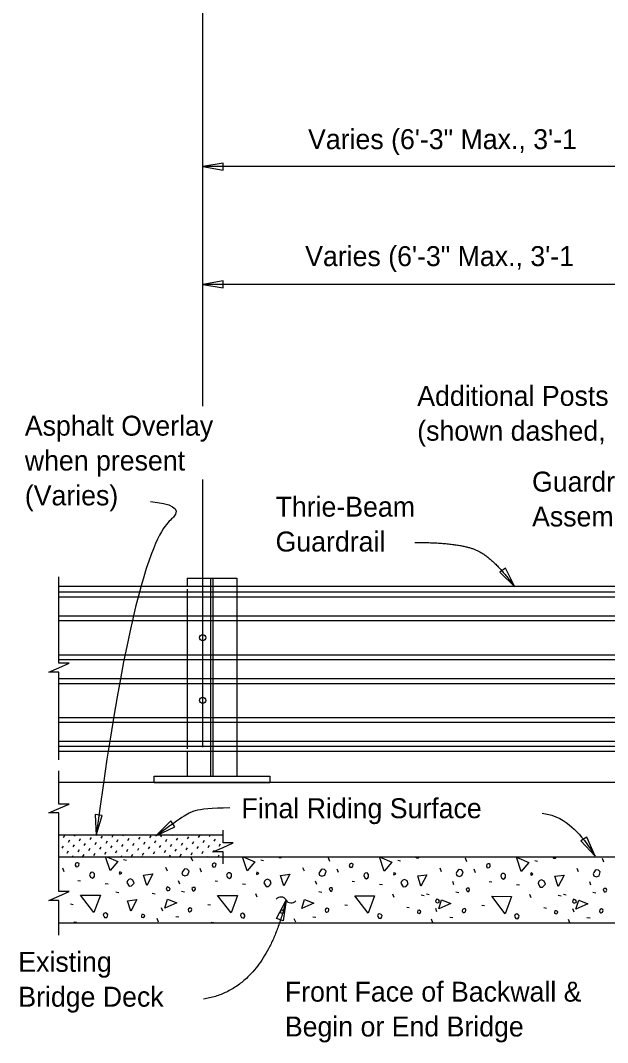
# Model space of a CAD drawing. Extents: x 21587 to 21656.3, y 56117.4 to 56157.3.
# Drawn here: x 21587.27 to 21593.21, y 56132.17 to 56142.5 of the extents above; entities that cross this region are included whole.
import ezdxf

# ---------------------------------------------------------------- set-up
doc = ezdxf.new("R2010")
doc.units = 0
for name, color, linetype in [('AdhocPoint_dp', 7, 'Continuous'), ('Border', 7, 'Continuous'), ('Patterning', 7, 'Continuous'), ('PlotBorder_dp', 7, 'Continuous'), ('SheetBorder_dp', 7, 'Continuous'), ('TextMisc', 7, 'Continuous')]:
    doc.layers.add(name, color=color, linetype=linetype)

msp = doc.modelspace()

# ---------------------------------------------------------------- linework, layer by layer
at = {"layer": 'AdhocPoint_dp'}
for p, q in [((21593.837, 56134.801), (21587.663, 56134.801)), ((21589.321, 56134.27), (21587.663, 56134.27)), ((21587.663, 56134.051), (21593.837, 56134.051)), ((21587.663, 56133.384), (21593.837, 56133.384))]:
    msp.add_line(p, q, dxfattribs=at)
at = {"layer": 'Border'}
for p, q in [((21588.96, 56136.864), (21589.46, 56136.864)), ((21588.96, 56136.864), (21588.96, 56136.78)), ((21589.46, 56136.864), (21589.46, 56136.78)), ((21599.759, 56136.78), (21587.663, 56136.78)), ((21587.663, 56136.725), (21599.759, 56136.725)), ((21587.663, 56136.676), (21599.759, 56136.676)), ((21587.663, 56136.484), (21599.759, 56136.484)), ((21587.663, 56136.435), (21599.759, 56136.435)), ((21587.663, 56136.091), (21599.759, 56136.091)), ((21587.663, 56136.043), (21599.759, 56136.043)), ((21587.663, 56135.85), (21599.759, 56135.85)), ((21587.663, 56135.802), (21599.759, 56135.802)), ((21587.663, 56135.458), (21599.759, 56135.458)), ((21587.663, 56135.41), (21599.759, 56135.41)), ((21587.663, 56135.217), (21599.759, 56135.217)), ((21587.663, 56135.169), (21599.759, 56135.169)), ((21599.759, 56135.113), (21587.663, 56135.113)), ((21588.96, 56135.114), (21588.96, 56134.864)), ((21589.46, 56135.113), (21589.46, 56134.864)), ((21588.626, 56134.864), (21589.793, 56134.864)), ((21588.626, 56134.801), (21588.626, 56134.864)), ((21588.626, 56134.801), (21589.793, 56134.801)), ((21588.96, 56134.864), (21589.46, 56134.864)), ((21589.793, 56134.864), (21589.793, 56134.801))]:
    msp.add_line(p, q, dxfattribs=at)
for centre in [(21589.116, 56136.263), (21589.116, 56135.63)]:
    msp.add_circle(centre, 0.0312, dxfattribs=at)
at = {"layer": 'Patterning'}
for p, q in [((21589.199, 56134.864), (21589.199, 56136.864)), ((21589.22, 56134.864), (21589.22, 56136.864)), ((21589.46, 56136.78), (21589.46, 56135.113)), ((21588.96, 56136.752), (21588.96, 56135.14))]:
    msp.add_line(p, q, dxfattribs=at)
at = {"layer": 'PlotBorder_dp'}
for p, q in [((21589.116, 56138.601), (21589.116, 56143.311)), ((21605.004, 56141.02), (21589.116, 56141.02)), ((21604.924, 56139.829), (21589.116, 56139.829)), ((21589.116, 56135.158), (21589.116, 56137.859))]:
    msp.add_line(p, q, dxfattribs=at)
for points in [[(21589.116, 56141.02), (21589.324, 56140.985), (21589.324, 56141.056)], [(21589.116, 56139.829), (21589.324, 56139.794), (21589.324, 56139.865)], [(21592.268, 56136.776), (21592.174, 56136.965), (21592.117, 56136.923)], [(21588.039, 56134.266), (21588.101, 56134.468), (21588.031, 56134.478)], [(21588.643, 56134.263), (21588.833, 56134.354), (21588.793, 56134.412)], [(21593.082, 56134.058), (21592.996, 56134.25), (21592.937, 56134.211)], [(21589.958, 56133.614), (21589.928, 56133.405), (21589.861, 56133.427)]]:
    msp.add_lwpolyline(points, close=True, dxfattribs=at)
for points in [[(21587.663, 56135.03), (21587.663, 56135.914), (21587.56, 56135.914), (21587.663, 56135.959), (21587.767, 56136.004), (21587.663, 56136.004), (21587.663, 56136.877)], [(21587.663, 56134.023), (21587.663, 56134.493), (21587.56, 56134.493), (21587.663, 56134.538), (21587.767, 56134.583), (21587.663, 56134.583), (21587.663, 56134.918)], [(21589.321, 56133.979), (21589.321, 56134.1), (21589.218, 56134.1), (21589.321, 56134.145), (21589.425, 56134.19), (21589.321, 56134.19), (21589.321, 56134.32)], [(21587.663, 56133.258), (21587.663, 56133.609), (21587.56, 56133.609), (21587.663, 56133.654), (21587.767, 56133.699), (21587.663, 56133.699), (21587.663, 56134.023)]]:
    msp.add_lwpolyline(points, dxfattribs=at)
for centre, start, end in [((21589.906, 56133.585), 30.0081, 141.7354), ((21590.009, 56133.644), 210.0081, 321.7354)]:
    msp.add_arc(centre, 0.0596, start, end, dxfattribs=at)
for points, degree in [([(21588.59, 56137.637), (21588.787, 56137.619), (21589.026, 56137.521), (21588.438, 56137.259), (21588.039, 56134.266)], 3), ([(21591.26, 56137.225), (21591.681, 56137.225), (21592.041, 56137.086), (21592.268, 56136.776)], 2), ([(21589.391, 56134.544), (21589.198, 56134.542), (21589.01, 56134.521), (21588.938, 56134.471), (21588.643, 56134.263)], 3), ([(21592.546, 56134.49), (21592.687, 56134.475), (21592.864, 56134.345), (21592.962, 56134.238), (21593.082, 56134.058)], 3), ([(21589.958, 56133.614), (21589.743, 56132.711), (21589.124, 56132.613)], 2)]:
    msp.add_open_spline(points, degree=degree, dxfattribs=at)
at = {"layer": 'TextMisc'}
for p, q in [((21587.71, 56134.247), (21587.723, 56134.27)), ((21587.759, 56134.199), (21587.772, 56134.221)), ((21587.821, 56134.26), (21587.826, 56134.27)), ((21587.87, 56134.212), (21587.883, 56134.234)), ((21587.918, 56134.163), (21587.931, 56134.185)), ((21587.98, 56134.225), (21587.993, 56134.247)), ((21588.029, 56134.176), (21588.042, 56134.198)), ((21588.091, 56134.237), (21588.104, 56134.26)), ((21588.14, 56134.189), (21588.153, 56134.211)), ((21588.202, 56134.25), (21588.213, 56134.27)), ((21588.25, 56134.202), (21588.263, 56134.224)), ((21588.299, 56134.153), (21588.312, 56134.175)), ((21588.312, 56134.263), (21588.316, 56134.27)), ((21588.361, 56134.215), (21588.374, 56134.237)), ((21588.41, 56134.166), (21588.423, 56134.188)), ((21588.472, 56134.228), (21588.485, 56134.25)), ((21588.52, 56134.179), (21588.533, 56134.201)), ((21588.582, 56134.241), (21588.595, 56134.263)), ((21588.631, 56134.192), (21588.644, 56134.214)), ((21588.693, 56134.253), (21588.702, 56134.27)), ((21588.742, 56134.205), (21588.755, 56134.227)), ((21588.791, 56134.156), (21588.804, 56134.178)), ((21588.804, 56134.266), (21588.806, 56134.27)), ((21588.852, 56134.218), (21588.865, 56134.24)), ((21588.901, 56134.169), (21588.914, 56134.191)), ((21588.963, 56134.231), (21588.976, 56134.253)), ((21589.012, 56134.182), (21589.025, 56134.204)), ((21589.074, 56134.244), (21589.087, 56134.266)), ((21589.122, 56134.195), (21589.135, 56134.217)), ((21589.184, 56134.256), (21589.192, 56134.27)), ((21589.233, 56134.208), (21589.246, 56134.23)), ((21589.282, 56134.159), (21589.295, 56134.181)), ((21589.295, 56134.269), (21589.295, 56134.27)), ((21587.697, 56134.137), (21587.71, 56134.159)), ((21587.746, 56134.088), (21587.759, 56134.11)), ((21587.808, 56134.15), (21587.821, 56134.172)), ((21587.857, 56134.101), (21587.87, 56134.123)), ((21587.906, 56134.052), (21587.918, 56134.074)), ((21587.967, 56134.114), (21587.98, 56134.136)), ((21588.016, 56134.065), (21588.029, 56134.087)), ((21588.078, 56134.127), (21588.091, 56134.149)), ((21588.127, 56134.078), (21588.14, 56134.1)), ((21588.189, 56134.14), (21588.202, 56134.162)), ((21588.237, 56134.091), (21588.25, 56134.113)), ((21588.348, 56134.104), (21588.361, 56134.126)), ((21588.397, 56134.055), (21588.41, 56134.078)), ((21588.459, 56134.117), (21588.472, 56134.139)), ((21588.508, 56134.068), (21588.52, 56134.09)), ((21588.569, 56134.13), (21588.582, 56134.152)), ((21588.618, 56134.081), (21588.631, 56134.103)), ((21588.68, 56134.143), (21588.693, 56134.165)), ((21588.729, 56134.094), (21588.742, 56134.116)), ((21588.839, 56134.107), (21588.852, 56134.129)), ((21588.888, 56134.058), (21588.901, 56134.081)), ((21588.95, 56134.12), (21588.963, 56134.142)), ((21588.999, 56134.071), (21589.012, 56134.093)), ((21589.061, 56134.133), (21589.074, 56134.155)), ((21589.109, 56134.084), (21589.122, 56134.106)), ((21589.171, 56134.146), (21589.184, 56134.168)), ((21589.22, 56134.097), (21589.233, 56134.119)), ((21589.271, 56134.051), (21589.282, 56134.071)), ((21589.331, 56134.11), (21589.331, 56134.11)), ((21587.802, 56134.051), (21587.808, 56134.062)), ((21588.188, 56134.051), (21588.189, 56134.052)), ((21588.291, 56134.051), (21588.299, 56134.065)), ((21588.317, 56134.024), (21588.345, 56134.017)), ((21588.678, 56134.051), (21588.68, 56134.055)), ((21588.781, 56134.051), (21588.791, 56134.068)), ((21589.015, 56134.008), (21589.001, 56134.043)), ((21589.167, 56134.051), (21589.171, 56134.058)), ((21589.702, 56134.02), (21589.73, 56134.013)), ((21590.4, 56134.004), (21590.386, 56134.04)), ((21591.086, 56134.017), (21591.114, 56134.01)), ((21591.784, 56134.001), (21591.77, 56134.036)), ((21592.471, 56134.013), (21592.499, 56134.006)), ((21593.169, 56133.997), (21593.155, 56134.033)), ((21587.718, 56133.899), (21587.704, 56133.934)), ((21588.759, 56133.907), (21588.745, 56133.942)), ((21589.103, 56133.895), (21589.089, 56133.931)), ((21590.143, 56133.904), (21590.129, 56133.939)), ((21590.488, 56133.892), (21590.473, 56133.927)), ((21591.528, 56133.9), (21591.514, 56133.935)), ((21591.872, 56133.888), (21591.858, 56133.924)), ((21592.913, 56133.897), (21592.899, 56133.932)), ((21587.856, 56133.811), (21587.881, 56133.807)), ((21588.132, 56133.782), (21588.162, 56133.777)), ((21588.884, 56133.775), (21588.872, 56133.808)), ((21589.241, 56133.807), (21589.266, 56133.803)), ((21589.517, 56133.779), (21589.547, 56133.773)), ((21590.269, 56133.771), (21590.257, 56133.805)), ((21590.625, 56133.803), (21590.65, 56133.8)), ((21590.901, 56133.775), (21590.931, 56133.77)), ((21591.654, 56133.767), (21591.641, 56133.801)), ((21592.01, 56133.8), (21592.035, 56133.796)), ((21592.286, 56133.772), (21592.316, 56133.766)), ((21593.038, 56133.764), (21593.026, 56133.798)), ((21588.239, 56133.698), (21588.267, 56133.691)), ((21588.607, 56133.684), (21588.635, 56133.677)), ((21588.903, 56133.703), (21588.933, 56133.697)), ((21589.665, 56133.644), (21589.653, 56133.678)), ((21590.288, 56133.699), (21590.318, 56133.694)), ((21591.05, 56133.641), (21591.037, 56133.674)), ((21591.324, 56133.667), (21591.352, 56133.66)), ((21591.376, 56133.677), (21591.404, 56133.67)), ((21591.672, 56133.696), (21591.703, 56133.69)), ((21592.434, 56133.637), (21592.422, 56133.671)), ((21592.708, 56133.664), (21592.737, 56133.657)), ((21592.761, 56133.674), (21592.789, 56133.667)), ((21593.057, 56133.692), (21593.087, 56133.687)), ((21587.782, 56133.574), (21587.808, 56133.568)), ((21589.167, 56133.57), (21589.193, 56133.565)), ((21590.551, 56133.567), (21590.578, 56133.561)), ((21591.936, 56133.563), (21591.962, 56133.558)), ((21588.713, 56133.502), (21588.7, 56133.535)), ((21591.177, 56133.542), (21591.203, 56133.537)), ((21591.482, 56133.495), (21591.47, 56133.528)), ((21592.562, 56133.538), (21592.588, 56133.533)), ((21592.867, 56133.491), (21592.854, 56133.525)), ((21588.67, 56133.392), (21588.656, 56133.428)), ((21588.843, 56133.448), (21588.875, 56133.445)), ((21590.055, 56133.389), (21590.041, 56133.424)), ((21590.228, 56133.445), (21590.26, 56133.441)), ((21591.44, 56133.385), (21591.426, 56133.42)), ((21591.612, 56133.441), (21591.644, 56133.438)), ((21592.823, 56133.384), (21592.81, 56133.417)), ((21592.997, 56133.438), (21593.029, 56133.434))]:
    msp.add_line(p, q, dxfattribs=at)
for points in [[(21587.828, 56133.966), (21587.837, 56133.95), (21587.856, 56133.952), (21587.865, 56133.964), (21587.867, 56133.984), (21587.854, 56133.989), (21587.845, 56133.991), (21587.835, 56133.987), (21587.831, 56133.984), (21587.828, 56133.966)], [(21588.18, 56133.911), (21588.134, 56134.051)], [(21588.148, 56134.051), (21588.257, 56134.003), (21588.18, 56133.911)], [(21588.503, 56134.051), (21588.504, 56134.049), (21588.502, 56134.051)], [(21588.504, 56134.049), (21588.525, 56134.049), (21588.528, 56134.051)], [(21589.212, 56133.963), (21589.221, 56133.947), (21589.241, 56133.948), (21589.25, 56133.961), (21589.251, 56133.98), (21589.239, 56133.986), (21589.23, 56133.987), (21589.22, 56133.984), (21589.216, 56133.98), (21589.212, 56133.963)], [(21589.564, 56133.908), (21589.518, 56134.051)], [(21589.525, 56134.051), (21589.642, 56134), (21589.564, 56133.908)], [(21589.886, 56134.051), (21589.889, 56134.045), (21589.885, 56134.049)], [(21589.889, 56134.045), (21589.91, 56134.045), (21589.916, 56134.051)], [(21590.597, 56133.959), (21590.606, 56133.943), (21590.625, 56133.945), (21590.634, 56133.957), (21590.636, 56133.977), (21590.624, 56133.982), (21590.615, 56133.984), (21590.604, 56133.98), (21590.601, 56133.977), (21590.597, 56133.959)], [(21590.949, 56133.904), (21590.901, 56134.051), (21591.027, 56133.996), (21590.949, 56133.904)], [(21591.27, 56134.051), (21591.274, 56134.041), (21591.27, 56134.045)], [(21591.274, 56134.041), (21591.295, 56134.041), (21591.304, 56134.051)], [(21591.982, 56133.955), (21591.991, 56133.94), (21592.01, 56133.941), (21592.019, 56133.954), (21592.021, 56133.973), (21592.008, 56133.978), (21592, 56133.98), (21591.989, 56133.977), (21591.985, 56133.973), (21591.982, 56133.955)], [(21592.334, 56133.901), (21592.286, 56134.047), (21592.411, 56133.993), (21592.334, 56133.901)], [(21592.653, 56134.051), (21592.653, 56134.05), (21592.658, 56134.038), (21592.655, 56134.041)], [(21592.658, 56134.038), (21592.679, 56134.038), (21592.69, 56134.049), (21592.689, 56134.051)], [(21587.973, 56133.867), (21587.983, 56133.846), (21588.001, 56133.835), (21588.015, 56133.846), (21588.022, 56133.856), (21588.022, 56133.878), (21588.006, 56133.894), (21587.987, 56133.892), (21587.978, 56133.883), (21587.973, 56133.867)], [(21588.279, 56133.876), (21588.298, 56133.885), (21588.291, 56133.892), (21588.279, 56133.897), (21588.273, 56133.885), (21588.279, 56133.876)], [(21588.552, 56133.76), (21588.518, 56133.865), (21588.612, 56133.877), (21588.552, 56133.76)], [(21588.913, 56133.87), (21588.936, 56133.858), (21588.966, 56133.87), (21588.978, 56133.907), (21588.96, 56133.925), (21588.937, 56133.93), (21588.927, 56133.923), (21588.914, 56133.904), (21588.906, 56133.888), (21588.913, 56133.87)], [(21589.357, 56133.864), (21589.368, 56133.842), (21589.386, 56133.832), (21589.4, 56133.842), (21589.407, 56133.853), (21589.407, 56133.874), (21589.391, 56133.89), (21589.372, 56133.888), (21589.363, 56133.879), (21589.357, 56133.864)], [(21589.663, 56133.872), (21589.683, 56133.881), (21589.676, 56133.888), (21589.663, 56133.894), (21589.658, 56133.881), (21589.663, 56133.872)], [(21589.937, 56133.757), (21589.903, 56133.861), (21589.997, 56133.874), (21589.937, 56133.757)], [(21590.297, 56133.866), (21590.32, 56133.854), (21590.35, 56133.866), (21590.363, 56133.904), (21590.345, 56133.921), (21590.322, 56133.927), (21590.311, 56133.919), (21590.299, 56133.9), (21590.29, 56133.884), (21590.297, 56133.866)], [(21590.742, 56133.86), (21590.753, 56133.839), (21590.77, 56133.828), (21590.785, 56133.839), (21590.792, 56133.849), (21590.792, 56133.871), (21590.776, 56133.887), (21590.756, 56133.885), (21590.747, 56133.876), (21590.742, 56133.86)], [(21591.048, 56133.869), (21591.067, 56133.878), (21591.06, 56133.885), (21591.048, 56133.89), (21591.043, 56133.878), (21591.048, 56133.869)], [(21591.321, 56133.753), (21591.288, 56133.858), (21591.381, 56133.87), (21591.321, 56133.753)], [(21591.682, 56133.863), (21591.705, 56133.851), (21591.735, 56133.863), (21591.747, 56133.9), (21591.73, 56133.918), (21591.707, 56133.923), (21591.696, 56133.916), (21591.684, 56133.897), (21591.675, 56133.881), (21591.682, 56133.863)], [(21592.127, 56133.856), (21592.137, 56133.835), (21592.155, 56133.825), (21592.169, 56133.835), (21592.176, 56133.846), (21592.176, 56133.867), (21592.16, 56133.883), (21592.141, 56133.881), (21592.132, 56133.872), (21592.127, 56133.856)], [(21592.433, 56133.865), (21592.452, 56133.874), (21592.445, 56133.881), (21592.433, 56133.887), (21592.427, 56133.874), (21592.433, 56133.865)], [(21592.706, 56133.75), (21592.672, 56133.854), (21592.766, 56133.866), (21592.706, 56133.75)], [(21593.067, 56133.859), (21593.09, 56133.847), (21593.12, 56133.859), (21593.132, 56133.897), (21593.114, 56133.914), (21593.091, 56133.919), (21593.081, 56133.912), (21593.068, 56133.893), (21593.06, 56133.877), (21593.067, 56133.859)], [(21588.349, 56133.791), (21588.372, 56133.754), (21588.395, 56133.756), (21588.404, 56133.765), (21588.424, 56133.784), (21588.411, 56133.814), (21588.386, 56133.828), (21588.369, 56133.821), (21588.355, 56133.807), (21588.349, 56133.791)], [(21589.734, 56133.788), (21589.757, 56133.75), (21589.78, 56133.752), (21589.789, 56133.761), (21589.808, 56133.78), (21589.796, 56133.811), (21589.771, 56133.825), (21589.753, 56133.818), (21589.739, 56133.803), (21589.734, 56133.788)], [(21591.119, 56133.784), (21591.142, 56133.747), (21591.165, 56133.749), (21591.173, 56133.757), (21591.193, 56133.777), (21591.181, 56133.807), (21591.156, 56133.821), (21591.138, 56133.814), (21591.124, 56133.8), (21591.119, 56133.784)], [(21592.503, 56133.78), (21592.526, 56133.743), (21592.549, 56133.745), (21592.558, 56133.754), (21592.578, 56133.773), (21592.565, 56133.803), (21592.54, 56133.818), (21592.523, 56133.811), (21592.509, 56133.796), (21592.503, 56133.78)], [(21588.017, 56133.487), (21587.883, 56133.664), (21588.082, 56133.662), (21588.017, 56133.487)], [(21588.758, 56133.711), (21588.77, 56133.71), (21588.782, 56133.715), (21588.786, 56133.726), (21588.781, 56133.734), (21588.77, 56133.741), (21588.758, 56133.747), (21588.751, 56133.733), (21588.747, 56133.722), (21588.758, 56133.711)], [(21589.014, 56133.715), (21589.025, 56133.704), (21589.036, 56133.712), (21589.043, 56133.722), (21589.039, 56133.74), (21589.03, 56133.742), (21589.018, 56133.74), (21589.007, 56133.729), (21589.014, 56133.715)], [(21589.402, 56133.483), (21589.267, 56133.66), (21589.467, 56133.658), (21589.402, 56133.483)], [(21590.399, 56133.712), (21590.41, 56133.701), (21590.42, 56133.708), (21590.427, 56133.719), (21590.424, 56133.736), (21590.415, 56133.738), (21590.403, 56133.736), (21590.392, 56133.726), (21590.399, 56133.712)], [(21591.784, 56133.708), (21591.794, 56133.697), (21591.805, 56133.704), (21591.812, 56133.715), (21591.809, 56133.733), (21591.8, 56133.734), (21591.787, 56133.733), (21591.777, 56133.722), (21591.784, 56133.708)], [(21593.169, 56133.704), (21593.179, 56133.694), (21593.19, 56133.701), (21593.197, 56133.712), (21593.193, 56133.729), (21593.184, 56133.731), (21593.172, 56133.729), (21593.161, 56133.719), (21593.169, 56133.704)], [(21588.389, 56133.502), (21588.355, 56133.606), (21588.449, 56133.619), (21588.389, 56133.502)], [(21588.732, 56133.531), (21588.76, 56133.623), (21588.854, 56133.586), (21588.732, 56133.531)], [(21590.116, 56133.528), (21590.145, 56133.62), (21590.238, 56133.582), (21590.116, 56133.528)], [(21590.786, 56133.48), (21590.652, 56133.657), (21590.852, 56133.655), (21590.786, 56133.48)], [(21591.479, 56133.589), (21591.491, 56133.587), (21591.503, 56133.592), (21591.507, 56133.603), (21591.502, 56133.612), (21591.491, 56133.619), (21591.479, 56133.624), (21591.472, 56133.61), (21591.468, 56133.6), (21591.479, 56133.589)], [(21591.501, 56133.524), (21591.529, 56133.616), (21591.623, 56133.579), (21591.501, 56133.524)], [(21592.171, 56133.476), (21592.037, 56133.653), (21592.236, 56133.651), (21592.171, 56133.476)], [(21592.863, 56133.585), (21592.876, 56133.584), (21592.888, 56133.589), (21592.892, 56133.6), (21592.886, 56133.608), (21592.876, 56133.615), (21592.863, 56133.621), (21592.856, 56133.607), (21592.853, 56133.596), (21592.863, 56133.585)], [(21592.886, 56133.521), (21592.914, 56133.613), (21593.008, 56133.575), (21592.886, 56133.521)], [(21588.116, 56133.455), (21588.125, 56133.439), (21588.146, 56133.436), (21588.155, 56133.452), (21588.158, 56133.466), (21588.15, 56133.475), (21588.134, 56133.483), (21588.118, 56133.478), (21588.112, 56133.462), (21588.116, 56133.455)], [(21588.497, 56133.442), (21588.516, 56133.437), (21588.529, 56133.446), (21588.53, 56133.458), (21588.527, 56133.462), (21588.513, 56133.469), (21588.5, 56133.467), (21588.499, 56133.455), (21588.497, 56133.442)], [(21588.979, 56133.496), (21588.986, 56133.496), (21589, 56133.503), (21589.006, 56133.519), (21589.004, 56133.528), (21588.99, 56133.535), (21588.972, 56133.524), (21588.969, 56133.514), (21588.972, 56133.503), (21588.979, 56133.496)], [(21589.501, 56133.452), (21589.509, 56133.436), (21589.531, 56133.432), (21589.54, 56133.448), (21589.543, 56133.462), (21589.534, 56133.471), (21589.518, 56133.48), (21589.502, 56133.475), (21589.497, 56133.459), (21589.501, 56133.452)], [(21589.9, 56133.487), (21589.92, 56133.482), (21589.932, 56133.491), (21589.934, 56133.503), (21589.93, 56133.506), (21589.916, 56133.514), (21589.904, 56133.512), (21589.902, 56133.499), (21589.9, 56133.487)], [(21590.364, 56133.492), (21590.371, 56133.492), (21590.385, 56133.499), (21590.39, 56133.515), (21590.389, 56133.524), (21590.374, 56133.531), (21590.357, 56133.521), (21590.353, 56133.51), (21590.357, 56133.499), (21590.364, 56133.492)], [(21590.885, 56133.448), (21590.894, 56133.432), (21590.915, 56133.429), (21590.924, 56133.445), (21590.928, 56133.459), (21590.919, 56133.468), (21590.903, 56133.476), (21590.887, 56133.471), (21590.882, 56133.455), (21590.885, 56133.448)], [(21591.285, 56133.483), (21591.304, 56133.478), (21591.317, 56133.487), (21591.318, 56133.499), (21591.315, 56133.503), (21591.301, 56133.51), (21591.288, 56133.508), (21591.287, 56133.496), (21591.285, 56133.483)], [(21591.748, 56133.489), (21591.756, 56133.489), (21591.77, 56133.496), (21591.775, 56133.512), (21591.773, 56133.521), (21591.759, 56133.528), (21591.741, 56133.517), (21591.738, 56133.506), (21591.741, 56133.496), (21591.748, 56133.489)], [(21592.27, 56133.445), (21592.279, 56133.429), (21592.3, 56133.425), (21592.309, 56133.441), (21592.312, 56133.455), (21592.304, 56133.464), (21592.288, 56133.473), (21592.272, 56133.468), (21592.266, 56133.452), (21592.27, 56133.445)], [(21592.669, 56133.48), (21592.689, 56133.475), (21592.701, 56133.483), (21592.703, 56133.496), (21592.7, 56133.499), (21592.685, 56133.506), (21592.673, 56133.505), (21592.671, 56133.492), (21592.669, 56133.48)], [(21593.133, 56133.485), (21593.14, 56133.485), (21593.154, 56133.492), (21593.16, 56133.508), (21593.158, 56133.517), (21593.144, 56133.524), (21593.126, 56133.514), (21593.123, 56133.503), (21593.126, 56133.492), (21593.133, 56133.485)], [(21587.841, 56133.384), (21587.84, 56133.388), (21587.817, 56133.39), (21587.815, 56133.384)], [(21589.225, 56133.384), (21589.225, 56133.384), (21589.202, 56133.386), (21589.201, 56133.384)]]:
    msp.add_lwpolyline(points, dxfattribs=at)

# ---------------------------------------------------------------- texts
at = {"layer": 'PlotBorder_dp'}
for s, p in [('Additional Posts required for Scheme 4 ', (21591.283, 56138.604)), ('Asphalt Overlay', (21587.319, 56138.303)), ('(shown dashed, number Reqd. varies)', (21591.283, 56138.252)), ('when present', (21587.319, 56137.951)), ('Guardrail Post ', (21592.443, 56137.738)), ('(Varies)', (21587.319, 56137.599)), ('Thrie-Beam ', (21589.852, 56137.485)), ('Assembly (Typ.)', (21592.443, 56137.386)), ('Guardrail', (21589.852, 56137.133)), ('Existing ', (21587.253, 56132.889)), ('Bridge Deck', (21587.253, 56132.537)), ('Front Face of Backwall &', (21589.946, 56132.588)), ('Begin or End Bridge', (21589.946, 56132.236))]:
    msp.add_text(s, height=0.2016, dxfattribs=at).set_placement(p)
at = {"layer": 'SheetBorder_dp'}
for s, p in [('Varies (6\'-3" Max., 3\'-1', (21590.18, 56141.196)), ('Varies (6\'-3" Max., 3\'-1', (21590.151, 56140.015)), ('Final Riding Surface', (21589.507, 56134.44))]:
    msp.add_text(s, height=0.2016, dxfattribs=at).set_placement(p)

doc.saveas('drawing.dxf')
